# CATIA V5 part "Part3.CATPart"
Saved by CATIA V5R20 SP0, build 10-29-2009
Part number: Part3
Bounding box of the stored display mesh (mm): x 0 to 400, y -400 to 400, z -400 to 400
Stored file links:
  E:\新建文件夹 (2)\Part3.CATPart
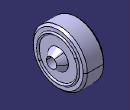
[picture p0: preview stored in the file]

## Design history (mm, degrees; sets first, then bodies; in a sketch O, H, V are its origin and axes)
Body1 (main body)
  Sketch1 on yz-plane, origin (0, 0, 0), H (0, 1, 0), V (0, 0, 1)
    circle A1 centre (0, 0) radius 400
    radius A1 = 400
  Pad1: profile Sketch1, direction (1, 0, 0), length 300
  Plane1: type Offset, RefPlane yz-plane, Offset 300
  Sketch2 on Plane1, origin (300, 0, 0), H (0, 1, 0), V (0, 0, 1)
    circle A1 centre (0, 0) radius 300
    point P1 (0, 300)
    point P2 (300, 0)
    coincidence: A1 P1, P1 V, P2 A1, P2 H
  Plane2: type Normal, Curve Sketch2.A1, RefPoint Sketch2.P2
  Sketch3 on Plane2, origin (0, 0, 0), H (1, 0, 0), V (0, 1, 0)
    circle A1 centre (300, 300) radius 20
    point P1 (300, 300)
    reference projected point E1 (300, 300) from Sketch2.P2
    radius A1 = 20
    coincidence: P1 E1
  Shaft1: profile Sketch3, axis X axis, angle 360
  Chamfer1: length 30, angle 45, on face of Pad1 from Sketch1.A1
  Plane3: type Offset, RefPlane Plane1, Offset 100
  Sketch4 on Plane3, origin (400, 0, 0), H (0, 1, 0), V (0, 0, 1)
    circle A1 centre (0, 0) radius 75
    point P1 (0, 75)
    coincidence: A1 P1, P1 V
  Sketch5 on Plane1, origin (300, 0, 0), H (0, 1, 0), V (0, 0, 1)
    circle A1 centre (0, 0) radius 150
    point P1 (0, 150)
    coincidence: A1 P1, P1 V
  Loft1: solid, Sections (Sketch4; Sketch5)
  Body2
    Sketch6 on yz-plane, origin (0, 0, 0), H (0, 1, 0), V (0, 0, 1)
      circle A1 centre (0, 0) radius 75
      point P1 (0, 75)
      radius A1 = 75
      coincidence: A1 P1, P1 V
    Pad2: profile Sketch6, direction (1, 0, 0), length 400
  Remove1: tool Body2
